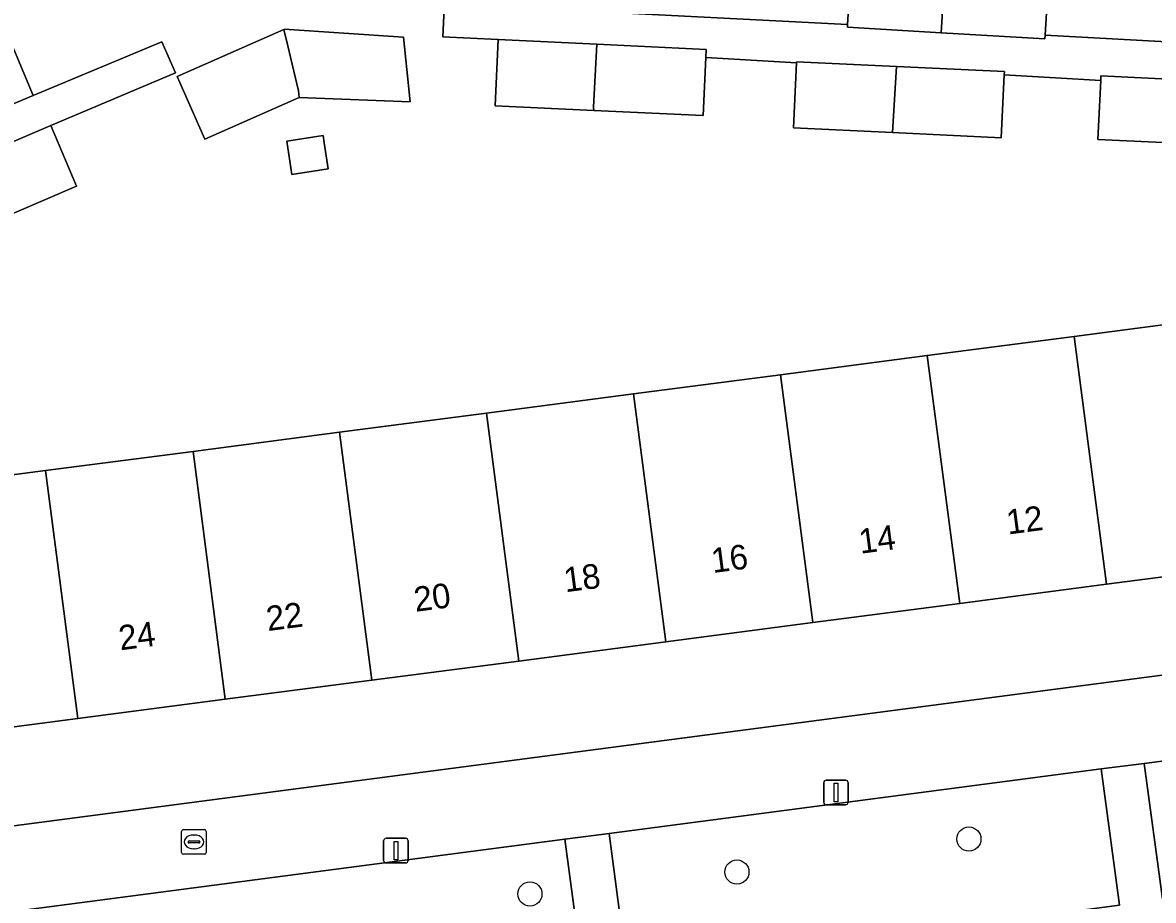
# Model space of a CAD drawing. Extents: x 162073 to 163043, y 381818 to 382561.
# Drawn here: x 162373.02 to 162418.89, y 382465.27 to 382500.88 of the extents above; entities that cross this region are included whole.
import ezdxf

# ---------------------------------------------------------------- set-up
doc = ezdxf.new("R2010")
doc.units = 0
for name, color, linetype in [('IMGEO_Boom', 7, 'Continuous'), ('IMGEO_Brandkraan', 7, 'Continuous'), ('IMGEO_Erf', 7, 'Continuous'), ('IMGEO_Groenvoorziening', 7, 'Continuous'), ('IMGEO_Lichtmast', 7, 'Continuous'), ('IMGEO_Pand', 7, 'Continuous'), ('IMGEO_Pand_nummerreeks', 7, 'Continuous'), ('IMGEO_Voetpad_open', 7, 'Continuous')]:
    doc.layers.add(name, color=color, linetype=linetype)

msp = doc.modelspace()

# ---------------------------------------------------------------- linework, layer by layer
at = {"layer": 'IMGEO_Boom'}
for centre in [(162411.408, 382467.759), (162401.998, 382466.42), (162393.602, 382465.53)]:
    msp.add_circle(centre, 0.489, dxfattribs=at)
at = {"layer": 'IMGEO_Brandkraan'}
for p, q in [((162379.475, 382467.216), (162379.475, 382468.068)), ((162379.55, 382468.142), (162380.402, 382468.142)), ((162379.963, 382467.922), (162379.988, 382467.922)), ((162380.476, 382468.068), (162380.476, 382467.216)), ((162379.734, 382467.636), (162379.734, 382467.648)), ((162380.172, 382467.599), (162379.774, 382467.599)), ((162379.777, 382467.685), (162380.175, 382467.685)), ((162379.986, 382467.362), (162379.961, 382467.362)), ((162380.218, 382467.648), (162380.218, 382467.636)), ((162380.402, 382467.142), (162379.55, 382467.142))]:
    msp.add_line(p, q, dxfattribs=at)
for points in [[(162379.475, 382467.216), (162379.475, 382468.068)], [(162379.55, 382468.142), (162380.402, 382468.142)], [(162380.476, 382468.068), (162380.476, 382467.216)], [(162380.402, 382467.142), (162379.55, 382467.142)]]:
    msp.add_lwpolyline(points, dxfattribs=at)
for centre, radius, start, end in [((162379.552, 382468.066), 0.0765, 91.552, 178.448), ((162379.552, 382468.066), 0.0765, 91.552, 178.448), ((162380.4, 382468.066), 0.0765, 1.552, 88.448), ((162380.4, 382468.066), 0.0765, 1.552, 88.448), ((162379.774, 382467.645), 0.0403, 85.8775, 175.7526), ((162379.771, 382467.635), 0.0366, 178.938, 274.7102), ((162380.175, 382467.642), 0.043, 264.8664, 352.4533), ((162380.179, 382467.647), 0.0386, 1.7309, 96.639), ((162379.552, 382467.218), 0.0765, 181.552, 268.448), ((162379.552, 382467.218), 0.0765, 181.552, 268.448), ((162380.4, 382467.218), 0.0765, 271.552, 358.448), ((162380.4, 382467.218), 0.0765, 271.552, 358.448)]:
    msp.add_arc(centre, radius, start, end, dxfattribs=at)
for centre, major_axis, ratio, start_param, end_param in [((162379.962, 382467.642), (-0.387, 0.002), 0.722429, 4.712389, 7.853982), ((162379.987, 382467.642), (-0.39, 0.002), 0.717154, 1.570796, 4.712389)]:
    msp.add_ellipse(centre, major_axis=major_axis, ratio=ratio, start_param=start_param, end_param=end_param, dxfattribs=at)
at = {"layer": 'IMGEO_Erf'}
for points in [[(162392.481, 382501.527), (162406.489, 382500.801), (162406.644, 382503.357)], [(162414.648, 382502.872), (162414.497, 382500.375), (162421.163, 382500.014)], [(162420.749, 382495.945), (162416.641, 382496.139), (162416.755, 382498.539), (162412.843, 382498.764), (162412.722, 382496.212), (162408.302, 382496.421), (162404.293, 382496.611), (162404.418, 382499.25), (162400.733, 382499.462), (162400.622, 382497.114), (162396.193, 382497.323), (162392.193, 382497.512), (162392.32, 382500.197), (162390.073, 382500.303), (162390.14, 382501.726)], [(162372.384, 382500.48), (162373.452, 382497.926), (162378.672, 382500.109), (162379.229, 382498.843), (162374.163, 382496.707), (162375.216, 382494.253), (162371.428, 382492.628)], [(162367.839, 382481.907), (162373.951, 382482.705), (162379.938, 382483.486), (162385.874, 382484.261), (162391.836, 382485.039), (162397.797, 382485.817), (162403.759, 382486.595), (162409.72, 382487.373), (162415.682, 382488.151), (162421.643, 382488.929), (162427.291, 382489.667), (162433.566, 382490.486), (162439.676, 382491.283), (162438.863, 382497.505), (162437.454, 382497.572), (162437.327, 382494.888), (162433.019, 382495.092), (162428.898, 382495.287), (162429.025, 382497.971)], [(162364.52, 382467.221), (162441.501, 382477.324), (162440.989, 382481.226), (162434.879, 382480.428), (162428.604, 382479.609), (162422.956, 382478.872), (162416.995, 382478.094), (162411.033, 382477.316), (162405.072, 382476.538), (162399.11, 382475.759), (162393.149, 382474.981), (162387.187, 382474.203), (162381.247, 382473.428), (162375.264, 382472.647), (162369.152, 382471.849)]]:
    msp.add_lwpolyline(points, dxfattribs=at)
for points in [[(162384.248, 382497.84), (162380.414, 382496.152), (162379.291, 382498.702), (162383.62, 382500.609), (162383.638, 382500.617), (162388.478, 382500.298), (162388.743, 382497.665)], [(162385.422, 382494.948), (162383.944, 382494.722), (162383.738, 382496.071), (162385.215, 382496.297), (162385.261, 382496)]]:
    msp.add_lwpolyline(points, close=True, dxfattribs=at)
at = {"layer": 'IMGEO_Groenvoorziening'}
for points in [[(162438.951, 382473.504), (162418.51, 382470.827), (162419.261, 382465.333), (162439.679, 382467.926)], [(162416.769, 382470.6), (162396.812, 382467.987), (162397.548, 382462.43), (162417.516, 382465.082)], [(162395.012, 382467.752), (162373.173, 382464.892), (162373.908, 382459.306), (162395.761, 382462.198)]]:
    msp.add_lwpolyline(points, close=True, dxfattribs=at)
at = {"layer": 'IMGEO_Lichtmast'}
for p, q in [((162405.52, 382469.246), (162405.52, 382470.046)), ((162405.52, 382470.046), (162405.52, 382469.246)), ((162405.62, 382470.146), (162406.41, 382470.146)), ((162406.41, 382470.146), (162405.62, 382470.146)), ((162406.51, 382470.046), (162406.51, 382469.246)), ((162406.51, 382469.246), (162406.51, 382470.046)), ((162406.41, 382469.146), (162405.62, 382469.146)), ((162405.62, 382469.146), (162406.41, 382469.146)), ((162387.769, 382467.789), (162388.559, 382467.789)), ((162388.559, 382467.789), (162387.769, 382467.789)), ((162387.669, 382466.889), (162387.669, 382467.689)), ((162387.669, 382467.689), (162387.669, 382466.889)), ((162388.659, 382467.689), (162388.659, 382466.889)), ((162388.659, 382466.889), (162388.659, 382467.689)), ((162388.559, 382466.789), (162387.769, 382466.789)), ((162387.769, 382466.789), (162388.559, 382466.789))]:
    msp.add_line(p, q, dxfattribs=at)
for points in [[(162405.94, 382470.021), (162406.09, 382470.021), (162406.09, 382469.271), (162405.94, 382469.271), (162405.94, 382470.021)], [(162388.089, 382467.664), (162388.239, 382467.664), (162388.239, 382466.914), (162388.089, 382466.914), (162388.089, 382467.664)]]:
    msp.add_lwpolyline(points, dxfattribs=at)
for centre, start, end in [((162405.62, 382470.046), 90, 180), ((162405.62, 382470.046), 90, 180), ((162406.41, 382470.046), 0, 90), ((162406.41, 382470.046), 360, 90), ((162405.62, 382469.246), 180, 270), ((162405.62, 382469.246), 180, 270), ((162406.41, 382469.246), 270, 0), ((162406.41, 382469.246), 270, 0), ((162387.769, 382467.689), 90, 180), ((162387.769, 382467.689), 90, 180), ((162388.559, 382467.689), 0, 90), ((162388.559, 382467.689), 360, 90), ((162387.769, 382466.889), 180, 270), ((162387.769, 382466.889), 180, 270), ((162388.559, 382466.889), 270, 0), ((162388.559, 382466.889), 270, 0)]:
    msp.add_arc(centre, 0.1, start, end, dxfattribs=at)
at = {"layer": 'IMGEO_Pand'}
for points in [[(162410.442, 382503.127), (162406.644, 382503.357), (162406.489, 382500.801), (162406.483, 382500.704), (162410.281, 382500.473)], [(162414.648, 382502.872), (162410.442, 382503.127), (162410.281, 382500.473), (162414.488, 382500.219), (162414.497, 382500.375)], [(162369.808, 382496.402), (162373.452, 382497.926), (162372.384, 382500.48), (162368.715, 382498.945)], [(162383.62, 382500.609), (162379.291, 382498.702), (162380.414, 382496.152), (162384.248, 382497.84), (162384.214, 382498.119), (162383.765, 382500)], [(162383.62, 382500.609), (162383.765, 382500), (162384.214, 382498.119), (162384.248, 382497.84), (162388.743, 382497.665), (162388.478, 382500.298), (162383.638, 382500.617)], [(162396.318, 382500.008), (162392.32, 382500.197), (162392.193, 382497.512), (162396.193, 382497.323), (162396.175, 382497.45)], [(162400.733, 382499.462), (162400.749, 382499.798), (162396.318, 382500.008), (162396.175, 382497.45), (162396.193, 382497.323), (162400.622, 382497.114)], [(162408.471, 382499.104), (162404.42, 382499.295), (162404.418, 382499.25), (162404.293, 382496.611), (162408.302, 382496.421)], [(162412.843, 382498.764), (162412.849, 382498.896), (162408.471, 382499.104), (162408.302, 382496.421), (162412.722, 382496.212)], [(162420.871, 382498.523), (162416.763, 382498.717), (162416.755, 382498.539), (162416.641, 382496.139), (162420.749, 382495.945)], [(162374.163, 382496.707), (162370.375, 382495.082), (162371.428, 382492.628), (162375.216, 382494.253)], [(162383.738, 382496.071), (162383.944, 382494.722), (162385.422, 382494.948), (162385.261, 382496), (162385.215, 382496.297)], [(162415.682, 382488.151), (162416.995, 382478.094), (162422.956, 382478.872), (162421.643, 382488.929)], [(162409.72, 382487.373), (162411.033, 382477.316), (162416.995, 382478.094), (162415.682, 382488.151)], [(162409.72, 382487.373), (162403.759, 382486.595), (162405.072, 382476.538), (162411.033, 382477.316)], [(162399.11, 382475.759), (162405.072, 382476.538), (162403.759, 382486.595), (162397.797, 382485.817)], [(162399.11, 382475.759), (162397.797, 382485.817), (162391.836, 382485.039), (162393.149, 382474.981)], [(162391.836, 382485.039), (162385.874, 382484.261), (162387.187, 382474.203), (162393.149, 382474.981)], [(162381.247, 382473.428), (162387.187, 382474.203), (162385.874, 382484.261), (162379.938, 382483.486), (162380.02, 382482.853)], [(162373.951, 382482.705), (162375.264, 382472.647), (162381.247, 382473.428), (162380.02, 382482.853), (162379.938, 382483.486)], [(162373.951, 382482.705), (162367.839, 382481.907), (162368.505, 382476.807), (162369.152, 382471.849), (162375.264, 382472.647)]]:
    msp.add_lwpolyline(points, close=True, dxfattribs=at)
at = {"layer": 'IMGEO_Voetpad_open'}
for points in [[(162345.602, 382517.307), (162349.916, 382511.715), (162352.427, 382508.458), (162354.939, 382505.198), (162358.069, 382501.145), (162360.58, 382497.888), (162363.092, 382494.628), (162364.021, 382493.592), (162366.744, 382493.524), (162370.375, 382495.082), (162374.163, 382496.707), (162379.229, 382498.843), (162378.672, 382500.109), (162373.452, 382497.926), (162369.808, 382496.402), (162366.074, 382494.84), (162364.77, 382494.958), (162355.304, 382507), (162352.301, 382510.897)], [(162390.14, 382501.726), (162390.073, 382500.303), (162392.32, 382500.197), (162396.318, 382500.008), (162400.749, 382499.798), (162400.733, 382499.462), (162404.418, 382499.25), (162404.42, 382499.295), (162408.471, 382499.104), (162412.849, 382498.896), (162412.843, 382498.764), (162416.755, 382498.539), (162416.763, 382498.717), (162420.871, 382498.523)], [(162421.163, 382500.014), (162414.497, 382500.375), (162414.488, 382500.219), (162410.281, 382500.473), (162406.483, 382500.704), (162406.489, 382500.801), (162392.481, 382501.527)], [(162418.51, 382470.827), (162438.951, 382473.504), (162440.79, 382473.744), (162458.233, 382476.248), (162464.468, 382477.086), (162463.612, 382484.979)], [(162459.406, 382479.673), (162442.944, 382477.513), (162441.501, 382477.324), (162364.52, 382467.221), (162358.274, 382466.401), (162352.438, 382465.635)], [(162462.024, 382470.821), (162441.489, 382468.16), (162440.79, 382473.744), (162438.951, 382473.504), (162439.679, 382467.926), (162419.261, 382465.333), (162418.51, 382470.827), (162416.769, 382470.6), (162417.516, 382465.082), (162397.548, 382462.43), (162396.812, 382467.987), (162395.012, 382467.752), (162395.761, 382462.198), (162373.908, 382459.306), (162373.173, 382464.892), (162371.398, 382464.66), (162372.148, 382459.072), (162351.881, 382456.381), (162351.85, 382453.585), (162354.468, 382453.854)], [(162348.481, 382466.366), (162347.775, 382461.567), (162371.398, 382464.66), (162373.173, 382464.892), (162395.012, 382467.752), (162396.812, 382467.987), (162416.769, 382470.6), (162418.51, 382470.827)]]:
    msp.add_lwpolyline(points, dxfattribs=at)

# ---------------------------------------------------------------- texts
at = {"layer": 'IMGEO_Pand_nummerreeks'}
for s, p in [('12', (162412.992, 382480.112)), ('14', (162407.008, 382479.332)), ('16', (162401.022, 382478.55)), ('18', (162395.039, 382477.769)), ('20', (162388.962, 382476.976)), ('22', (162382.97, 382476.194)), ('24', (162376.986, 382475.413))]:
    msp.add_text(s, height=1, rotation=7.4369, dxfattribs=at).set_placement(p)

doc.saveas('drawing.dxf')
